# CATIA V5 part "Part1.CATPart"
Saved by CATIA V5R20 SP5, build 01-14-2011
Part number: Part1
Material "Lead": density 11340 kg/m3, Young's modulus 1.6e+10 Pa, Poisson ratio 0.44, thermal expansion 2.89e-05 1/K
Bounding box of the stored display mesh (mm): x -25 to 25, y -25 to 25, z -60 to 50
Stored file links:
  E:\Part1.CATPart
  C:\Program Files\Dassault Systemes\B20\intel_a\startup\materials\Catalog.CATMaterial
  C:\Program Files\Dassault Systemes\B20\intel_a\startup\materials\lead.jpg
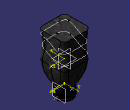
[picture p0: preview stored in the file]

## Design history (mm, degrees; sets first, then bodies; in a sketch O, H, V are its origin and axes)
Set1
  Sketch1 on xy-plane, origin (0, 0, 0), H (1, 0, 0), V (0, 1, 0)
    line L1 (25, 25) -> (25, -25)
    line L2 (25, -25) -> (-25, -25)
    line L3 (-25, -25) -> (-25, 25)
    line L4 (-25, 25) -> (25, 25)
    length L4 = 50
    length L1 = 50
    vertical: L1 V, L3 V
    horizontal: L2 H, L4 H
    equidistance: L1 L3 O, L2 L4 O
  Sketch2 on start face of Pad1, origin (0, 0, 0), H (1, 0, 0), V (0, -1, 0)
    point P1 (25, 0)
    distance P1 O = 25
    coincidence: P1 H
  Sketch3 on Plane1, origin (0, 0, -40), H (1, 0, 0), V (0, 1, 0)
  Sketch4 on Plane1, origin (0, 0, -40), H (1, 0, 0), V (0, 1, 0)
    point P1 (15, 0)
    distance P1 O = 15
    coincidence: P1 H
  Sketch5 on face of Pad1 from Sketch1.L3, origin (-25, 0, 0), H (0, -1, 0), V (0, 0, 1)
    spline S1 through (-40, 20) (-10, 10) (10, 20) (50, 10)
    spline S2 through (-40, 40) (-10, 30) (10, 40) (40, 30)
  Extrude1: Element1 Sketch5, Lim1 10, Lim2 60
  MultiSel1: CommonCtxFeats ({extract ExtractElem face of Pad1 from Sketch1.L2}; {extract ExtractElem face of Fillet1}; {extract ExtractElem face of Pad1 from Sketch1.L3}; {extract ExtractElem face of Fillet1}; {extract ExtractElem face of Pad1 from Sketch1.L4}; {extract ExtractElem face of Fillet1}; {extract ExtractElem face of Pad1 from Sketch1.L1}; {extract ExtractElem face of Fillet1})
Body1 (main body), material "Lead"
  Pad1: profile Sketch1, direction (0, 0, 1), length 50
  Fillet1: on edge [face of Pad1 from Sketch1.L4 | face of Pad1 from Sketch1.L1]; edge [face of Pad1 from Sketch1.L3 | face of Pad1 from Sketch1.L4]; edge [face of Pad1 from Sketch1.L2 | face of Pad1 from Sketch1.L3]; edge [face of Pad1 from Sketch1.L1 | face of Pad1 from Sketch1.L2]
  Plane1: type Offset, RefPlane xy-plane, Offset -40
  Sketch6 on Plane1, origin (0, 0, -40), H (1, 0, 0), V (0, 1, 0)
    circle A1 centre (0, 0) radius 15
    point P1 (15, 0)
    radius A1 = 15
    coincidence: A1 P1, P1 H
  Pad2: profile Sketch6, direction (0, 0, -1), length 20
  Loft1: solid, Sections (edge [face of Pad2 from Sketch6.A1 | start face of Pad2]; {boundary Boundary {extract ExtractElem start face of Pad1}}), EndFace start face of Pad1
  Shell1: ExtOffset 0, Face end face of Pad2, IntOffset 1
  Plane2: type Offset, RefPlane Plane1, Offset -2
  Sketch7 on Plane2, origin (0, 0, -42), H (1, 0, 0), V (0, 1, 0)
    point P1 (0, 15)
    distance P1 O = 15
    coincidence: P1 V
  Helix1: Direction Z axis, RefPoint Sketch7, Pitch 3, Height 16, TaperAngle 0
  Point1: type OnCurve, Support Helix1, RefPoint vertex of Helix1, Length -6.218
  Line1: type PtDir, RefPoint vertex of Helix1, Direction (1, 0, 0), Start 0, End 10
  Connect1: Curve1 Line1, Point1 vertex of Line1, Tension1 1, Curve2 Helix1, Point2 Point1, Tension2 1
  Plane3: type Normal, Curve Connect1, RefPoint vertex of Connect1
  Circle1: type CtrRad, Start 0, End 180, Center vertex of Connect1, Support Plane3, Radius 1, FirstDirection (0, 1, 0)
  Rib1: profile Circle1, centre curve Connect1
  Sketch8 on xy-plane, origin (0, 0, 0), H (1, 0, 0), V (0, 1, 0)
    circle A1 centre (0, 0) radius 14
    radius A1 = 14
  Pocket1: profile Sketch8, direction (0, 0, -1), length 80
